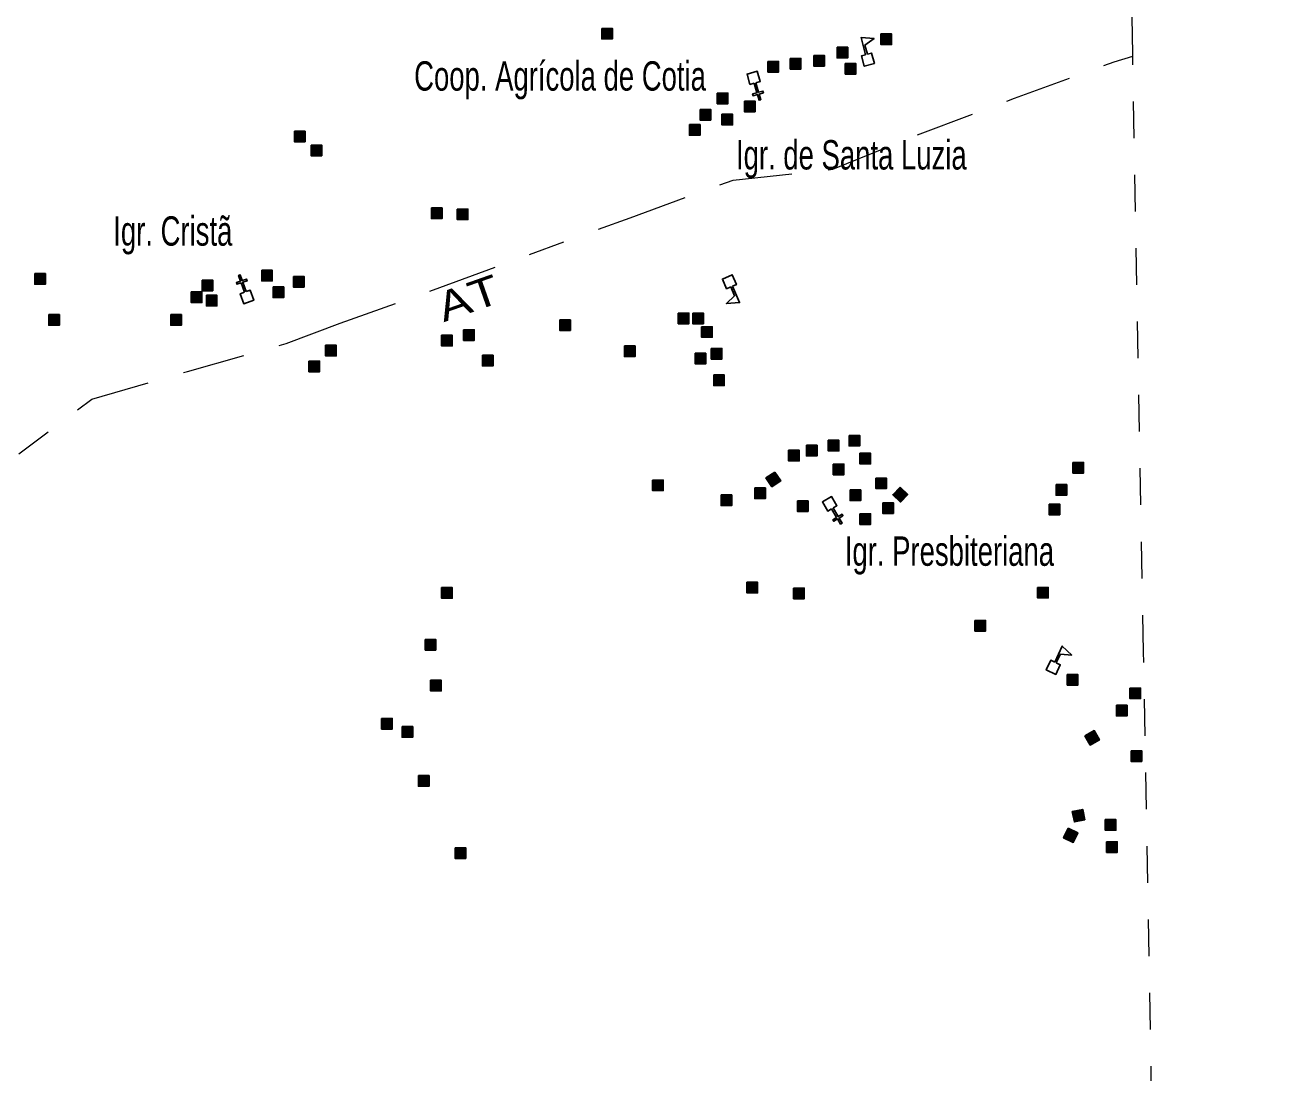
# Model space of a CAD drawing. Extents: x 220.8 to 246.7, y 7287.6 to 7315.8.
# Drawn here: x 243.25 to 246.651, y 7306.491 to 7309.345 of the extents above; entities that cross this region are included whole.
import ezdxf
from ezdxf.enums import TextEntityAlignment as Align

# ---------------------------------------------------------------- set-up
doc = ezdxf.new("R2010")
doc.units = 0
doc.header["$LTSCALE"] = 0.032
doc.linetypes.add('DOT_DASHED', pattern=[7.7, 5, -1.2, 0.3, -1.2])
doc.linetypes.add('SHORT_DASHED', pattern=[2.7, 1.5, -1.2])
for name, color, linetype, lineweight in [('2', 7, 'Continuous', 25), ('4', 7, 'Continuous', 25), ('56', 7, 'DOT_DASHED', 13), ('58', 7, 'SHORT_DASHED', 13), ('6', 7, 'Continuous', 25)]:
    doc.layers.add(name, color=color, linetype=linetype, lineweight=lineweight)
doc.layers.add('61', color=7, linetype='Continuous')

msp = doc.modelspace()

# ---------------------------------------------------------------- hatches: boundary and pattern name
at = {"layer": '2'}
for points in [[(244.8216, 7309.3354), (244.8506, 7309.3354), (244.8506, 7309.3064), (244.8216, 7309.3064)], [(245.5823, 7309.3201), (245.6113, 7309.3201), (245.6113, 7309.2911), (245.5823, 7309.2911)], [(245.463, 7309.284), (245.492, 7309.284), (245.492, 7309.255), (245.463, 7309.255)], [(245.2743, 7309.2452), (245.3033, 7309.2452), (245.3033, 7309.2162), (245.2743, 7309.2162)], [(245.3353, 7309.2535), (245.3643, 7309.2535), (245.3643, 7309.2245), (245.3353, 7309.2245)], [(245.3991, 7309.2618), (245.4281, 7309.2618), (245.4281, 7309.2328), (245.3991, 7309.2328)], [(245.4852, 7309.2396), (245.5142, 7309.2396), (245.5142, 7309.2106), (245.4852, 7309.2106)], [(245.1363, 7309.1589), (245.1653, 7309.1589), (245.1653, 7309.1299), (245.1363, 7309.1299)], [(245.0895, 7309.1143), (245.1185, 7309.1143), (245.1185, 7309.0853), (245.0895, 7309.0853)], [(245.2105, 7309.137), (245.2395, 7309.137), (245.2395, 7309.108), (245.2105, 7309.108)], [(245.0606, 7309.0731), (245.0896, 7309.0731), (245.0896, 7309.0441), (245.0606, 7309.0441)], [(245.149, 7309.1015), (245.178, 7309.1015), (245.178, 7309.0725), (245.149, 7309.0725)], [(243.984, 7309.0552), (244.013, 7309.0552), (244.013, 7309.0262), (243.984, 7309.0262)], [(244.0294, 7309.0173), (244.0584, 7309.0173), (244.0584, 7308.9883), (244.0294, 7308.9883)], [(244.3576, 7308.8459), (244.3866, 7308.8459), (244.3866, 7308.8169), (244.3576, 7308.8169)], [(244.4279, 7308.8431), (244.4569, 7308.8431), (244.4569, 7308.8141), (244.4279, 7308.8141)], [(243.2765, 7308.667), (243.3055, 7308.667), (243.3055, 7308.638), (243.2765, 7308.638)], [(243.8949, 7308.6764), (243.9239, 7308.6764), (243.9239, 7308.6474), (243.8949, 7308.6474)], [(243.7324, 7308.6494), (243.7614, 7308.6494), (243.7614, 7308.6204), (243.7324, 7308.6204)], [(243.9261, 7308.6308), (243.9551, 7308.6308), (243.9551, 7308.6018), (243.9261, 7308.6018)], [(243.9814, 7308.6596), (244.0104, 7308.6596), (244.0104, 7308.6306), (243.9814, 7308.6306)], [(243.703, 7308.6171), (243.732, 7308.6171), (243.732, 7308.5881), (243.703, 7308.5881)], [(243.7441, 7308.6082), (243.7731, 7308.6082), (243.7731, 7308.5792), (243.7441, 7308.5792)], [(243.3148, 7308.5553), (243.3438, 7308.5553), (243.3438, 7308.5263), (243.3148, 7308.5263)], [(243.6471, 7308.5553), (243.6761, 7308.5553), (243.6761, 7308.5263), (243.6471, 7308.5263)], [(244.707, 7308.5411), (244.736, 7308.5411), (244.736, 7308.5121), (244.707, 7308.5121)], [(245.0301, 7308.5597), (245.0591, 7308.5597), (245.0591, 7308.5307), (245.0301, 7308.5307)], [(245.0695, 7308.5597), (245.0985, 7308.5597), (245.0985, 7308.5307), (245.0695, 7308.5307)], [(244.385, 7308.499), (244.414, 7308.499), (244.414, 7308.47), (244.385, 7308.47)], [(244.4452, 7308.514), (244.4742, 7308.514), (244.4742, 7308.485), (244.4452, 7308.485)], [(245.0936, 7308.5225), (245.1226, 7308.5225), (245.1226, 7308.4935), (245.0936, 7308.4935)], [(244.069, 7308.4719), (244.098, 7308.4719), (244.098, 7308.4429), (244.069, 7308.4429)], [(244.8834, 7308.4699), (244.9124, 7308.4699), (244.9124, 7308.4409), (244.8834, 7308.4409)], [(245.1199, 7308.4633), (245.1489, 7308.4633), (245.1489, 7308.4343), (245.1199, 7308.4343)], [(244.0236, 7308.4286), (244.0526, 7308.4286), (244.0526, 7308.3996), (244.0236, 7308.3996)], [(244.4964, 7308.4448), (244.5254, 7308.4448), (244.5254, 7308.4158), (244.4964, 7308.4158)], [(245.0761, 7308.4502), (245.1051, 7308.4502), (245.1051, 7308.4212), (245.0761, 7308.4212)], [(245.1265, 7308.3911), (245.1555, 7308.3911), (245.1555, 7308.3621), (245.1265, 7308.3621)], [(245.4955, 7308.2264), (245.5245, 7308.2264), (245.5245, 7308.1974), (245.4955, 7308.1974)], [(245.3792, 7308.1993), (245.4082, 7308.1993), (245.4082, 7308.1703), (245.3792, 7308.1703)], [(245.4387, 7308.2128), (245.4677, 7308.2128), (245.4677, 7308.1838), (245.4387, 7308.1838)], [(245.3305, 7308.1858), (245.3595, 7308.1858), (245.3595, 7308.1568), (245.3305, 7308.1568)], [(245.5252, 7308.1777), (245.5542, 7308.1777), (245.5542, 7308.1487), (245.5252, 7308.1487)], [(245.2931, 7308.1265), (245.3092, 7308.1024), (245.2852, 7308.0862), (245.269, 7308.1102)], [(245.4522, 7308.1479), (245.4812, 7308.1479), (245.4812, 7308.1189), (245.4522, 7308.1189)], [(246.1056, 7308.1526), (246.1346, 7308.1526), (246.1346, 7308.1236), (246.1056, 7308.1236)], [(244.9602, 7308.1047), (244.9892, 7308.1047), (244.9892, 7308.0757), (244.9602, 7308.0757)], [(245.5684, 7308.1101), (245.5974, 7308.1101), (245.5974, 7308.0811), (245.5684, 7308.0811)], [(246.0597, 7308.0923), (246.0887, 7308.0923), (246.0887, 7308.0633), (246.0597, 7308.0633)], [(245.1467, 7308.0641), (245.1757, 7308.0641), (245.1757, 7308.0351), (245.1467, 7308.0351)], [(245.2386, 7308.0831), (245.2676, 7308.0831), (245.2676, 7308.0541), (245.2386, 7308.0541)], [(245.4982, 7308.0777), (245.5272, 7308.0777), (245.5272, 7308.0487), (245.4982, 7308.0487)], [(245.6343, 7308.0854), (245.6554, 7308.0655), (245.6355, 7308.0444), (245.6144, 7308.0643)], [(245.3549, 7308.0479), (245.3839, 7308.0479), (245.3839, 7308.0189), (245.3549, 7308.0189)], [(245.5874, 7308.0425), (245.6164, 7308.0425), (245.6164, 7308.0135), (245.5874, 7308.0135)], [(246.0404, 7308.0391), (246.0694, 7308.0391), (246.0694, 7308.0101), (246.0404, 7308.0101)], [(245.5252, 7308.0128), (245.5542, 7308.0128), (245.5542, 7307.9838), (245.5252, 7307.9838)], [(245.217, 7307.8262), (245.246, 7307.8262), (245.246, 7307.7972), (245.217, 7307.7972)], [(244.385, 7307.8115), (244.414, 7307.8115), (244.414, 7307.7825), (244.385, 7307.7825)], [(245.3441, 7307.81), (245.3731, 7307.81), (245.3731, 7307.781), (245.3441, 7307.781)], [(246.009, 7307.8122), (246.038, 7307.8122), (246.038, 7307.7832), (246.009, 7307.7832)], [(245.8385, 7307.7222), (245.8675, 7307.7222), (245.8675, 7307.6932), (245.8385, 7307.6932)], [(244.3404, 7307.6704), (244.3694, 7307.6704), (244.3694, 7307.6414), (244.3404, 7307.6414)], [(244.3553, 7307.5591), (244.3843, 7307.5591), (244.3843, 7307.5301), (244.3553, 7307.5301)], [(246.0898, 7307.5747), (246.1188, 7307.5747), (246.1188, 7307.5457), (246.0898, 7307.5457)], [(246.2607, 7307.5379), (246.2897, 7307.5379), (246.2897, 7307.5089), (246.2607, 7307.5089)], [(246.2239, 7307.4909), (246.2529, 7307.4909), (246.2529, 7307.4619), (246.2239, 7307.4619)], [(244.2216, 7307.4551), (244.2506, 7307.4551), (244.2506, 7307.4261), (244.2216, 7307.4261)], [(244.2773, 7307.4329), (244.3063, 7307.4329), (244.3063, 7307.4039), (244.2773, 7307.4039)], [(246.1382, 7307.4075), (246.1635, 7307.4217), (246.1777, 7307.3965), (246.1525, 7307.3823)], [(246.2641, 7307.3669), (246.2931, 7307.3669), (246.2931, 7307.3379), (246.2641, 7307.3379)], [(244.3219, 7307.2992), (244.3509, 7307.2992), (244.3509, 7307.2702), (244.3219, 7307.2702)], [(246.1037, 7307.2015), (246.1321, 7307.2072), (246.1378, 7307.1788), (246.1093, 7307.1731)], [(246.1937, 7307.1793), (246.2227, 7307.1793), (246.2227, 7307.1503), (246.1937, 7307.1503)], [(246.0923, 7307.1557), (246.1185, 7307.1433), (246.1061, 7307.1171), (246.0799, 7307.1295)], [(244.4221, 7307.1025), (244.4511, 7307.1025), (244.4511, 7307.0735), (244.4221, 7307.0735)], [(246.1971, 7307.1189), (246.2261, 7307.1189), (246.2261, 7307.0899), (246.1971, 7307.0899)]]:
    msp.add_hatch(color=256, dxfattribs=at).paths.add_polyline_path(points)

# ---------------------------------------------------------------- linework, layer by layer
for points in [[(244.8216, 7309.3354), (244.8506, 7309.3354), (244.8506, 7309.3064), (244.8216, 7309.3064)], [(245.5823, 7309.3201), (245.6113, 7309.3201), (245.6113, 7309.2911), (245.5823, 7309.2911)], [(245.463, 7309.284), (245.492, 7309.284), (245.492, 7309.255), (245.463, 7309.255)], [(245.2743, 7309.2452), (245.3033, 7309.2452), (245.3033, 7309.2162), (245.2743, 7309.2162)], [(245.3353, 7309.2535), (245.3643, 7309.2535), (245.3643, 7309.2245), (245.3353, 7309.2245)], [(245.3991, 7309.2618), (245.4281, 7309.2618), (245.4281, 7309.2328), (245.3991, 7309.2328)], [(245.4852, 7309.2396), (245.5142, 7309.2396), (245.5142, 7309.2106), (245.4852, 7309.2106)], [(245.1363, 7309.1589), (245.1653, 7309.1589), (245.1653, 7309.1299), (245.1363, 7309.1299)], [(245.0895, 7309.1143), (245.1185, 7309.1143), (245.1185, 7309.0853), (245.0895, 7309.0853)], [(245.2105, 7309.137), (245.2395, 7309.137), (245.2395, 7309.108), (245.2105, 7309.108)], [(245.0606, 7309.0731), (245.0896, 7309.0731), (245.0896, 7309.0441), (245.0606, 7309.0441)], [(245.149, 7309.1015), (245.178, 7309.1015), (245.178, 7309.0725), (245.149, 7309.0725)], [(243.984, 7309.0552), (244.013, 7309.0552), (244.013, 7309.0262), (243.984, 7309.0262)], [(244.0294, 7309.0173), (244.0584, 7309.0173), (244.0584, 7308.9883), (244.0294, 7308.9883)], [(244.3576, 7308.8459), (244.3866, 7308.8459), (244.3866, 7308.8169), (244.3576, 7308.8169)], [(244.4279, 7308.8431), (244.4569, 7308.8431), (244.4569, 7308.8141), (244.4279, 7308.8141)], [(243.2765, 7308.667), (243.3055, 7308.667), (243.3055, 7308.638), (243.2765, 7308.638)], [(243.8949, 7308.6764), (243.9239, 7308.6764), (243.9239, 7308.6474), (243.8949, 7308.6474)], [(243.7324, 7308.6494), (243.7614, 7308.6494), (243.7614, 7308.6204), (243.7324, 7308.6204)], [(243.9261, 7308.6308), (243.9551, 7308.6308), (243.9551, 7308.6018), (243.9261, 7308.6018)], [(243.9814, 7308.6596), (244.0104, 7308.6596), (244.0104, 7308.6306), (243.9814, 7308.6306)], [(243.703, 7308.6171), (243.732, 7308.6171), (243.732, 7308.5881), (243.703, 7308.5881)], [(243.7441, 7308.6082), (243.7731, 7308.6082), (243.7731, 7308.5792), (243.7441, 7308.5792)], [(243.3148, 7308.5553), (243.3438, 7308.5553), (243.3438, 7308.5263), (243.3148, 7308.5263)], [(243.6471, 7308.5553), (243.6761, 7308.5553), (243.6761, 7308.5263), (243.6471, 7308.5263)], [(244.707, 7308.5411), (244.736, 7308.5411), (244.736, 7308.5121), (244.707, 7308.5121)], [(245.0301, 7308.5597), (245.0591, 7308.5597), (245.0591, 7308.5307), (245.0301, 7308.5307)], [(245.0695, 7308.5597), (245.0985, 7308.5597), (245.0985, 7308.5307), (245.0695, 7308.5307)], [(244.385, 7308.499), (244.414, 7308.499), (244.414, 7308.47), (244.385, 7308.47)], [(244.4452, 7308.514), (244.4742, 7308.514), (244.4742, 7308.485), (244.4452, 7308.485)], [(245.0936, 7308.5225), (245.1226, 7308.5225), (245.1226, 7308.4935), (245.0936, 7308.4935)], [(244.069, 7308.4719), (244.098, 7308.4719), (244.098, 7308.4429), (244.069, 7308.4429)], [(244.8834, 7308.4699), (244.9124, 7308.4699), (244.9124, 7308.4409), (244.8834, 7308.4409)], [(245.1199, 7308.4633), (245.1489, 7308.4633), (245.1489, 7308.4343), (245.1199, 7308.4343)], [(244.0236, 7308.4286), (244.0526, 7308.4286), (244.0526, 7308.3996), (244.0236, 7308.3996)], [(244.4964, 7308.4448), (244.5254, 7308.4448), (244.5254, 7308.4158), (244.4964, 7308.4158)], [(245.0761, 7308.4502), (245.1051, 7308.4502), (245.1051, 7308.4212), (245.0761, 7308.4212)], [(245.1265, 7308.3911), (245.1555, 7308.3911), (245.1555, 7308.3621), (245.1265, 7308.3621)], [(245.4955, 7308.2264), (245.5245, 7308.2264), (245.5245, 7308.1974), (245.4955, 7308.1974)], [(245.3792, 7308.1993), (245.4082, 7308.1993), (245.4082, 7308.1703), (245.3792, 7308.1703)], [(245.4387, 7308.2128), (245.4677, 7308.2128), (245.4677, 7308.1838), (245.4387, 7308.1838)], [(245.3305, 7308.1858), (245.3595, 7308.1858), (245.3595, 7308.1568), (245.3305, 7308.1568)], [(245.5252, 7308.1777), (245.5542, 7308.1777), (245.5542, 7308.1487), (245.5252, 7308.1487)], [(245.2931, 7308.1265), (245.3092, 7308.1024), (245.2852, 7308.0862), (245.269, 7308.1102)], [(245.4522, 7308.1479), (245.4812, 7308.1479), (245.4812, 7308.1189), (245.4522, 7308.1189)], [(246.1056, 7308.1526), (246.1346, 7308.1526), (246.1346, 7308.1236), (246.1056, 7308.1236)], [(244.9602, 7308.1047), (244.9892, 7308.1047), (244.9892, 7308.0757), (244.9602, 7308.0757)], [(245.5684, 7308.1101), (245.5974, 7308.1101), (245.5974, 7308.0811), (245.5684, 7308.0811)], [(246.0597, 7308.0923), (246.0887, 7308.0923), (246.0887, 7308.0633), (246.0597, 7308.0633)], [(245.1467, 7308.0641), (245.1757, 7308.0641), (245.1757, 7308.0351), (245.1467, 7308.0351)], [(245.2386, 7308.0831), (245.2676, 7308.0831), (245.2676, 7308.0541), (245.2386, 7308.0541)], [(245.4982, 7308.0777), (245.5272, 7308.0777), (245.5272, 7308.0487), (245.4982, 7308.0487)], [(245.6343, 7308.0854), (245.6554, 7308.0655), (245.6355, 7308.0444), (245.6144, 7308.0643)], [(245.3549, 7308.0479), (245.3839, 7308.0479), (245.3839, 7308.0189), (245.3549, 7308.0189)], [(245.5874, 7308.0425), (245.6164, 7308.0425), (245.6164, 7308.0135), (245.5874, 7308.0135)], [(246.0404, 7308.0391), (246.0694, 7308.0391), (246.0694, 7308.0101), (246.0404, 7308.0101)], [(245.5252, 7308.0128), (245.5542, 7308.0128), (245.5542, 7307.9838), (245.5252, 7307.9838)], [(245.217, 7307.8262), (245.246, 7307.8262), (245.246, 7307.7972), (245.217, 7307.7972)], [(244.385, 7307.8115), (244.414, 7307.8115), (244.414, 7307.7825), (244.385, 7307.7825)], [(245.3441, 7307.81), (245.3731, 7307.81), (245.3731, 7307.781), (245.3441, 7307.781)], [(246.009, 7307.8122), (246.038, 7307.8122), (246.038, 7307.7832), (246.009, 7307.7832)], [(245.8385, 7307.7222), (245.8675, 7307.7222), (245.8675, 7307.6932), (245.8385, 7307.6932)], [(244.3404, 7307.6704), (244.3694, 7307.6704), (244.3694, 7307.6414), (244.3404, 7307.6414)], [(244.3553, 7307.5591), (244.3843, 7307.5591), (244.3843, 7307.5301), (244.3553, 7307.5301)], [(246.0898, 7307.5747), (246.1188, 7307.5747), (246.1188, 7307.5457), (246.0898, 7307.5457)], [(246.2607, 7307.5379), (246.2897, 7307.5379), (246.2897, 7307.5089), (246.2607, 7307.5089)], [(246.2239, 7307.4909), (246.2529, 7307.4909), (246.2529, 7307.4619), (246.2239, 7307.4619)], [(244.2216, 7307.4551), (244.2506, 7307.4551), (244.2506, 7307.4261), (244.2216, 7307.4261)], [(244.2773, 7307.4329), (244.3063, 7307.4329), (244.3063, 7307.4039), (244.2773, 7307.4039)], [(246.1382, 7307.4075), (246.1635, 7307.4217), (246.1777, 7307.3965), (246.1525, 7307.3823)], [(246.2641, 7307.3669), (246.2931, 7307.3669), (246.2931, 7307.3379), (246.2641, 7307.3379)], [(244.3219, 7307.2992), (244.3509, 7307.2992), (244.3509, 7307.2702), (244.3219, 7307.2702)], [(246.1037, 7307.2015), (246.1321, 7307.2072), (246.1378, 7307.1788), (246.1093, 7307.1731)], [(246.1937, 7307.1793), (246.2227, 7307.1793), (246.2227, 7307.1503), (246.1937, 7307.1503)], [(246.0923, 7307.1557), (246.1185, 7307.1433), (246.1061, 7307.1171), (246.0799, 7307.1295)], [(244.4221, 7307.1025), (244.4511, 7307.1025), (244.4511, 7307.0735), (244.4221, 7307.0735)], [(246.1971, 7307.1189), (246.2261, 7307.1189), (246.2261, 7307.0899), (246.1971, 7307.0899)]]:
    msp.add_lwpolyline(points, close=True, dxfattribs=at)
at = {"layer": '4'}
for points in [[(245.5406, 7309.2634), (245.528, 7309.3101), (245.5637, 7309.3077), (245.5385, 7309.2899), (245.5453, 7309.2647)], [(245.5453, 7309.2647), (245.557, 7309.2678), (245.5646, 7309.2398), (245.5366, 7309.2323), (245.529, 7309.2603), (245.5406, 7309.2634)], [(245.173, 7308.6307), (245.1619, 7308.6258), (245.1503, 7308.6524), (245.1769, 7308.664), (245.1885, 7308.6374), (245.1775, 7308.6326)], [(245.1775, 7308.6326), (245.1969, 7308.5883), (245.1612, 7308.5853), (245.1835, 7308.6067), (245.173, 7308.6307)], [(246.0557, 7307.6083), (246.0762, 7307.6522), (246.102, 7307.6274), (246.0712, 7307.6299), (246.0602, 7307.6062)], [(246.0602, 7307.6062), (246.0711, 7307.6011), (246.0589, 7307.5749), (246.0326, 7307.5871), (246.0448, 7307.6134), (246.0557, 7307.6083)]]:
    msp.add_lwpolyline(points, dxfattribs=at)
at = {"layer": '56'}
msp.add_lwpolyline([(243.025, 7308.0201), (243.432, 7308.3246), (243.6926, 7308.4008), (243.962, 7308.4769), (244.1084, 7308.5325), (244.3807, 7308.6292), (244.8989, 7308.8195), (245.18, 7308.922), (245.451, 7308.9514), (245.6823, 7309.0452), (245.9458, 7309.1448), (246.2181, 7309.2445), (246.2686, 7309.2595)], dxfattribs=at)
at = {"layer": '58'}
msp.add_lwpolyline([(246.6507, 7288.0853), (246.6212, 7289.7146), (246.5917, 7291.3439), (246.5622, 7292.9732), (246.5328, 7294.6024), (246.5034, 7296.2317), (246.4739, 7297.861), (246.4446, 7299.4903), (246.4152, 7301.1196), (246.3858, 7302.7489), (246.3565, 7304.3782), (246.3272, 7306.0075), (246.2979, 7307.6367), (246.2685, 7309.266), (246.2393, 7310.8953), (246.21, 7312.5246), (246.1808, 7314.1539), (246.1516, 7315.7832)], dxfattribs=at)
at = {"layer": '6'}
for points in [[(245.237, 7309.186), (245.2253, 7309.1827), (245.2175, 7309.2106), (245.2454, 7309.2185), (245.2533, 7309.1906), (245.2416, 7309.1873)], [(245.2416, 7309.1873), (245.249, 7309.1612), (245.2606, 7309.1645), (245.2619, 7309.1598), (245.2503, 7309.1565), (245.2547, 7309.1408), (245.2501, 7309.1394), (245.2456, 7309.1552), (245.234, 7309.1519), (245.2327, 7309.1567), (245.2443, 7309.1599), (245.237, 7309.186)], [(243.8478, 7308.6163), (243.8389, 7308.6419), (243.8275, 7308.638), (243.8259, 7308.6426), (243.8373, 7308.6465), (243.832, 7308.662), (243.8365, 7308.6636), (243.8419, 7308.6481), (243.8533, 7308.6521), (243.8549, 7308.6474), (243.8435, 7308.6435), (243.8523, 7308.6179)], [(243.8523, 7308.6179), (243.8638, 7308.6218), (243.8732, 7308.5944), (243.8458, 7308.5849), (243.8363, 7308.6123), (243.8478, 7308.6163)], [(245.4479, 7308.0261), (245.4375, 7308.02), (245.4228, 7308.045), (245.4478, 7308.0597), (245.4625, 7308.0347), (245.4521, 7308.0286)], [(245.4521, 7308.0286), (245.4658, 7308.0052), (245.4762, 7308.0113), (245.4787, 7308.0071), (245.4683, 7308.001), (245.4765, 7307.9868), (245.4724, 7307.9844), (245.4641, 7307.9985), (245.4537, 7307.9924), (245.4512, 7307.9966), (245.4616, 7308.0028), (245.4479, 7308.0261)]]:
    msp.add_lwpolyline(points, dxfattribs=at)

# ---------------------------------------------------------------- texts
at = {"layer": '61', "width": 0.7}
for s, p in [('Coop. Agrícola de Cotia', (245.1054, 7309.1657)), ('Igr. Cristã', (243.815, 7308.7432))]:
    msp.add_text(s, height=0.08, dxfattribs=at).set_placement(p, align=Align.RIGHT)
for s, p in [('Igr. de Santa Luzia', (245.1873, 7308.9508)), ('Igr. Presbiteriana', (245.4838, 7307.8709))]:
    msp.add_text(s, height=0.08, dxfattribs=at).set_placement(p)
at = {"layer": '61', "width": 1.25}
msp.add_text('AT', height=0.08, rotation=19.376, dxfattribs=at).set_placement((244.4714, 7308.5627), align=Align.CENTER)

doc.saveas('drawing.dxf')
